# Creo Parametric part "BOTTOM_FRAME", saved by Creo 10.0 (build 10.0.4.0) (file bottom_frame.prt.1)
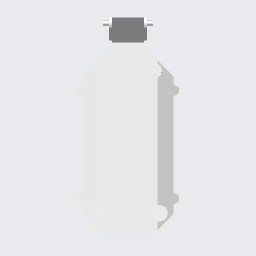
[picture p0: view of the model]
Units: millimeter Kilogram Sec (mmKs); MM, KILOGRAM, SECS

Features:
  1. datum plane "RIGHT"
  2. datum plane "TOP"
  3. datum plane "FRONT"
  4. coordinate system
  5. extrusion "Extrude 1"
  6. extrusion "Extrude 2"
  7. extruded cut "Extrude 3"
  8. extrusion "Extrude 4"
  9. extruded cut "Extrude 5"
  10. extrusion "Extrude 6"
  11. extrusion "Extrude 7"
  12. extrusion "Extrude 8"
  13. extrusion "Extrude 9"
  14. extruded cut "Extrude 10"
  15. extruded cut "Extrude 11"
  16. round "Round 1"
  17. extrusion "Extrude 12"
  18. extruded cut "Extrude 13"
  19. extrusion "Extrude 14"
  20. extruded cut "Extrude 15"
  21. extruded cut "Extrude 16"
  22. extrusion "Extrude 17"
  23. extruded cut "Extrude 18"
  24. extruded cut "Extrude 19"
  25. extruded cut "Extrude 20"
  26. extruded cut "Extrude 21"
  27. mirror "Mirror 1"
  28. extrusion "Extrude 22"

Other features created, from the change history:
  feature "Copy Geometry id 1204"
  feature "Copy Geometry id 1519"
  mirror "Mirror 1" (2 times)
  extrusion "Extrude 1 (2)" (2 times)
  extrusion "Extrude 2 (2)"
  extruded cut "Extrude 3 (2)"
  extrusion "Extrude 4 (2)"
  extruded cut "Extrude 5 (2)"
  extrusion "Extrude 6 (2)"
  extrusion "Extrude 7 (2)"
  extrusion "Extrude 8 (2)"
  extrusion "Extrude 9 (2)"
  extruded cut "Extrude 10 (2)"
  extruded cut "Extrude 11 (2)"
  round "Round 1 (2)"
  extrusion "Extrude 12 (2)"
  extruded cut "Extrude 13 (2)"
  extrusion "Extrude 14 (2)"
  extruded cut "Extrude 15 (2)"
  extruded cut "Extrude 16 (2)"
  extrusion "Extrude 17 (2)"
  extruded cut "Extrude 18 (2)"
  extruded cut "Extrude 19 (2)"
  extruded cut "Extrude 20 (2)"
  extruded cut "Extrude 21 (2)"

Other named items: RIGHT_1, TOP_1, FRONT_1, PRT_CSYS_DEF_2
